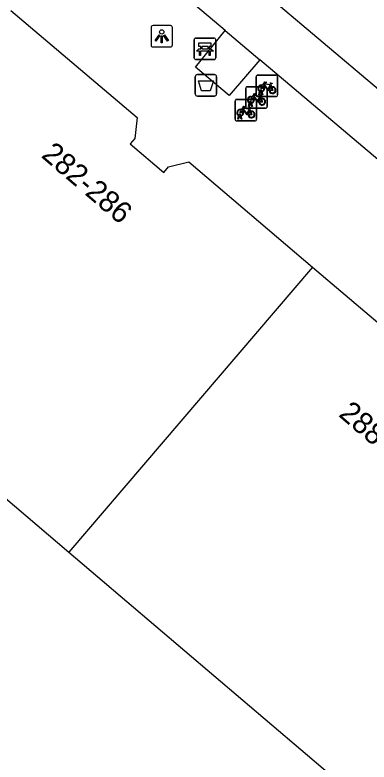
# Model space of a CAD drawing. Extents: x 162347 to 162868, y 381221 to 381813.
# Drawn here: x 162737.04 to 162753.52, y 381577.53 to 381612.3 of the extents above; entities that cross this region are included whole.
import ezdxf

# ---------------------------------------------------------------- set-up
doc = ezdxf.new("R2010")
doc.units = 0
for name, color, linetype in [('IMGEO_Afvalbak', 7, 'Continuous'), ('IMGEO_Bank', 7, 'Continuous'), ('IMGEO_Fietsenrek', 7, 'Continuous'), ('IMGEO_Fietspad_gesloten', 7, 'Continuous'), ('IMGEO_Lichtpunt', 7, 'Continuous'), ('IMGEO_Pand', 7, 'Continuous'), ('IMGEO_Pand_nummerreeks', 7, 'Continuous'), ('IMGEO_Voetpad_open', 7, 'Continuous')]:
    doc.layers.add(name, color=color, linetype=linetype)

msp = doc.modelspace()

# ---------------------------------------------------------------- linework, layer by layer
at = {"layer": 'IMGEO_Afvalbak'}
for p, q in [((162745.432, 381608.623), (162745.432, 381609.423)), ((162745.432, 381609.423), (162745.432, 381608.623)), ((162745.532, 381609.523), (162746.322, 381609.523)), ((162746.322, 381609.523), (162745.532, 381609.523)), ((162746.422, 381609.423), (162746.422, 381608.623)), ((162746.422, 381608.623), (162746.422, 381609.423)), ((162746.322, 381608.523), (162745.532, 381608.523)), ((162745.532, 381608.523), (162746.322, 381608.523))]:
    msp.add_line(p, q, dxfattribs=at)
msp.add_lwpolyline([(162745.575, 381609.237), (162746.279, 381609.237), (162746.13, 381608.767), (162745.724, 381608.767), (162745.575, 381609.237)], dxfattribs=at)
for centre, start, end in [((162745.532, 381609.423), 90, 180), ((162745.532, 381609.423), 90, 180), ((162746.322, 381609.423), 0, 90), ((162746.322, 381609.423), 360, 90), ((162745.532, 381608.623), 180, 270), ((162745.532, 381608.623), 180, 270), ((162746.322, 381608.623), 270, 0), ((162746.322, 381608.623), 270, 0)]:
    msp.add_arc(centre, 0.1, start, end, dxfattribs=at)
at = {"layer": 'IMGEO_Bank'}
for p, q in [((162745.382, 381610.295), (162745.382, 381611.136)), ((162745.382, 381611.136), (162745.382, 381610.295)), ((162745.457, 381611.22), (162746.298, 381611.22)), ((162746.298, 381611.22), (162745.457, 381611.22)), ((162746.382, 381611.145), (162746.382, 381610.304)), ((162746.382, 381610.304), (162746.382, 381611.145)), ((162746.079, 381610.618), (162745.686, 381610.618)), ((162745.691, 381610.726), (162745.691, 381610.832)), ((162745.735, 381610.832), (162745.735, 381610.726)), ((162746.023, 381610.838), (162745.741, 381610.838)), ((162745.741, 381610.72), (162746.023, 381610.72)), ((162746.029, 381610.726), (162746.029, 381610.832)), ((162746.073, 381610.832), (162746.073, 381610.726)), ((162746.307, 381610.22), (162745.466, 381610.22)), ((162745.466, 381610.22), (162746.307, 381610.22))]:
    msp.add_line(p, q, dxfattribs=at)
for points in [[(162745.685, 381610.838), (162745.599, 381610.838), (162745.599, 381610.999), (162746.162, 381610.999), (162746.162, 381610.838), (162746.079, 381610.838)], [(162745.629, 381610.618), (162745.487, 381610.618), (162745.599, 381610.72), (162745.685, 381610.72)], [(162745.679, 381610.611), (162745.679, 381610.404), (162745.636, 381610.404), (162745.636, 381610.611)], [(162746.079, 381610.72), (162746.162, 381610.72), (162746.274, 381610.618), (162746.135, 381610.618)], [(162746.129, 381610.611), (162746.129, 381610.404), (162746.085, 381610.404), (162746.085, 381610.611)]]:
    msp.add_lwpolyline(points, dxfattribs=at)
for centre, radius, start, end in [((162745.46, 381611.142), 0.0779, 92.4484, 184.2845), ((162745.46, 381611.142), 0.0779, 92.4484, 184.2845), ((162746.304, 381611.142), 0.0779, 2.4484, 94.2845), ((162746.304, 381611.142), 0.0779, 2.4484, 94.2845), ((162745.629, 381610.611), 0.00671, 2.8957, 87.1043), ((162745.686, 381610.611), 0.00671, 92.8957, 177.1043), ((162745.684, 381610.831), 0.00671, 2.8957, 87.1043), ((162745.684, 381610.727), 0.00671, 272.8957, 357.1043), ((162745.741, 381610.831), 0.00671, 92.8957, 177.1043), ((162745.741, 381610.727), 0.00671, 182.8957, 267.1043), ((162746.023, 381610.831), 0.00671, 2.8957, 87.1043), ((162746.023, 381610.727), 0.00671, 272.8957, 357.1043), ((162746.08, 381610.831), 0.00671, 92.8957, 177.1043), ((162746.08, 381610.727), 0.00671, 182.8957, 267.1043), ((162746.078, 381610.611), 0.00671, 2.8957, 87.1043), ((162746.135, 381610.611), 0.00671, 92.8957, 177.1043), ((162745.46, 381610.298), 0.0779, 182.4484, 274.2845), ((162745.46, 381610.298), 0.0779, 182.4484, 274.2845), ((162746.304, 381610.298), 0.0779, 272.4484, 4.2845), ((162746.304, 381610.298), 0.0779, 272.4484, 4.2845)]:
    msp.add_arc(centre, radius, start, end, dxfattribs=at)
at = {"layer": 'IMGEO_Fietsenrek'}
for p, q in [((162748.261, 381608.573), (162748.261, 381609.414)), ((162748.261, 381609.414), (162748.261, 381608.573)), ((162748.336, 381609.498), (162749.177, 381609.498)), ((162749.177, 381609.498), (162748.336, 381609.498)), ((162749.261, 381609.423), (162749.261, 381608.582)), ((162749.261, 381608.582), (162749.261, 381609.423)), ((162747.778, 381608.036), (162747.778, 381608.877)), ((162747.778, 381608.877), (162747.778, 381608.036)), ((162747.853, 381608.961), (162748.694, 381608.961)), ((162748.694, 381608.961), (162747.853, 381608.961)), ((162748.778, 381608.886), (162748.778, 381608.045)), ((162748.778, 381608.045), (162748.778, 381608.886)), ((162748.948, 381609.047), (162748.984, 381608.952)), ((162749.186, 381608.498), (162748.345, 381608.498)), ((162748.345, 381608.498), (162749.186, 381608.498)), ((162748.388, 381608.582), (162748.427, 381608.742)), ((162748.422, 381608.582), (162748.388, 381608.582)), ((162748.457, 381608.73), (162748.422, 381608.582)), ((162748.465, 381608.51), (162748.501, 381608.415)), ((162748.499, 381608.754), (162748.498, 381608.758)), ((162748.54, 381608.582), (162748.506, 381608.724)), ((162748.53, 381608.765), (162748.531, 381608.758)), ((162748.538, 381608.728), (162748.573, 381608.582)), ((162748.573, 381608.582), (162748.54, 381608.582)), ((162747.283, 381607.442), (162747.283, 381608.283)), ((162747.283, 381608.283), (162747.283, 381607.442)), ((162747.358, 381608.367), (162748.199, 381608.367)), ((162748.199, 381608.367), (162747.358, 381608.367)), ((162747.905, 381608.045), (162747.944, 381608.205)), ((162747.974, 381608.193), (162747.939, 381608.045)), ((162748.016, 381608.217), (162748.015, 381608.221)), ((162748.057, 381608.045), (162748.023, 381608.187)), ((162748.047, 381608.228), (162748.048, 381608.221)), ((162748.055, 381608.191), (162748.09, 381608.045)), ((162748.283, 381608.292), (162748.283, 381607.451)), ((162748.283, 381607.451), (162748.283, 381608.292)), ((162748.703, 381607.961), (162747.862, 381607.961)), ((162747.862, 381607.961), (162748.703, 381607.961)), ((162747.939, 381608.045), (162747.905, 381608.045)), ((162747.97, 381607.916), (162748.006, 381607.821)), ((162748.09, 381608.045), (162748.057, 381608.045)), ((162747.41, 381607.451), (162747.449, 381607.611)), ((162747.444, 381607.451), (162747.41, 381607.451)), ((162747.479, 381607.599), (162747.444, 381607.451)), ((162747.521, 381607.623), (162747.52, 381607.627)), ((162747.562, 381607.451), (162747.528, 381607.593)), ((162747.552, 381607.634), (162747.553, 381607.627)), ((162747.56, 381607.597), (162747.595, 381607.451)), ((162747.595, 381607.451), (162747.562, 381607.451)), ((162748.208, 381607.367), (162747.367, 381607.367)), ((162747.367, 381607.367), (162748.208, 381607.367))]:
    msp.add_line(p, q, dxfattribs=at)
for points in [[(162748.595, 381608.972), (162748.543, 381608.882), (162748.503, 381608.857), (162748.504, 381608.904), (162748.559, 381608.998)], [(162748.574, 381609.024), (162748.669, 381609.188), (162748.755, 381609.174), (162748.757, 381609.165), (162748.701, 381609.154), (162748.674, 381609.109), (162748.93, 381609.068)], [(162748.87, 381608.78), (162748.82, 381608.78), (162748.629, 381609.031), (162748.61, 381608.999)], [(162748.917, 381609.043), (162748.66, 381609.084), (162748.643, 381609.055), (162748.81, 381608.835), (162748.917, 381609.043)], [(162748.965, 381608.945), (162748.935, 381609.022), (162748.826, 381608.804), (162748.869, 381608.804)], [(162748.899, 381608.804), (162749.019, 381608.803), (162748.975, 381608.917)], [(162748.995, 381608.924), (162749.05, 381608.779), (162748.9, 381608.779)], [(162748.93, 381609.068), (162748.955, 381609.117), (162748.949, 381609.121), (162748.926, 381609.125), (162748.914, 381609.132), (162748.913, 381609.135), (162748.915, 381609.14), (162749.01, 381609.125), (162749.012, 381609.115), (162749.002, 381609.102), (162748.99, 381609.096), (162748.976, 381609.102), (162748.948, 381609.047)], [(162748.091, 381608.487), (162748.186, 381608.651), (162748.272, 381608.637), (162748.274, 381608.628), (162748.218, 381608.617), (162748.191, 381608.572), (162748.447, 381608.531)], [(162748.387, 381608.243), (162748.337, 381608.243), (162748.146, 381608.494), (162748.127, 381608.462)], [(162748.434, 381608.506), (162748.177, 381608.547), (162748.16, 381608.518), (162748.327, 381608.298), (162748.434, 381608.506)], [(162748.447, 381608.531), (162748.472, 381608.58), (162748.466, 381608.584), (162748.443, 381608.588), (162748.431, 381608.595), (162748.43, 381608.598), (162748.432, 381608.603), (162748.527, 381608.588), (162748.529, 381608.578), (162748.519, 381608.565), (162748.507, 381608.559), (162748.493, 381608.565), (162748.465, 381608.51)], [(162748.112, 381608.435), (162748.06, 381608.345), (162748.02, 381608.32), (162748.021, 381608.367), (162748.076, 381608.461)], [(162748.482, 381608.408), (162748.452, 381608.485), (162748.343, 381608.267), (162748.386, 381608.267)], [(162748.416, 381608.267), (162748.536, 381608.266), (162748.492, 381608.38)], [(162748.512, 381608.387), (162748.567, 381608.242), (162748.417, 381608.242)], [(162747.617, 381607.841), (162747.565, 381607.751), (162747.525, 381607.726), (162747.526, 381607.773), (162747.581, 381607.867)], [(162747.596, 381607.893), (162747.691, 381608.057), (162747.777, 381608.043), (162747.779, 381608.034), (162747.723, 381608.023), (162747.696, 381607.978), (162747.952, 381607.937)], [(162747.892, 381607.649), (162747.842, 381607.649), (162747.651, 381607.9), (162747.632, 381607.868)], [(162747.939, 381607.912), (162747.682, 381607.953), (162747.665, 381607.924), (162747.832, 381607.704), (162747.939, 381607.912)], [(162747.987, 381607.814), (162747.957, 381607.891), (162747.848, 381607.673), (162747.891, 381607.673)], [(162747.952, 381607.937), (162747.977, 381607.986), (162747.971, 381607.99), (162747.948, 381607.994), (162747.936, 381608.001), (162747.935, 381608.004), (162747.937, 381608.009), (162748.032, 381607.994), (162748.034, 381607.984), (162748.024, 381607.971), (162748.012, 381607.965), (162747.998, 381607.971), (162747.97, 381607.916)], [(162747.921, 381607.673), (162748.041, 381607.672), (162747.997, 381607.786)], [(162748.017, 381607.793), (162748.072, 381607.648), (162747.922, 381607.648)]]:
    msp.add_lwpolyline(points, dxfattribs=at)
for centre, radius, start, end in [((162748.339, 381609.42), 0.0779, 92.4484, 184.2845), ((162748.339, 381609.42), 0.0779, 92.4484, 184.2845), ((162749.183, 381609.42), 0.0779, 2.4484, 94.2845), ((162749.183, 381609.42), 0.0779, 2.4484, 94.2845), ((162747.856, 381608.883), 0.0779, 92.4484, 184.2845), ((162747.856, 381608.883), 0.0779, 92.4484, 184.2845), ((162748.501, 381608.883), 0.159, 62.6766, 242.1369), ((162748.501, 381608.883), 0.129, 63.3192, 238.903), ((162748.501, 381608.883), 0.129, 283.6043, 43.4302), ((162748.501, 381608.883), 0.159, 283.5766, 46.6042), ((162748.7, 381608.883), 0.0779, 2.4484, 94.2845), ((162748.7, 381608.883), 0.0779, 2.4484, 94.2845), ((162749.028, 381608.799), 0.159, 113.3408, 178.3217), ((162749.028, 381608.799), 0.159, 187.0065, 105.7708), ((162749.028, 381608.799), 0.129, 113.923, 177.9556), ((162749.028, 381608.799), 0.129, 188.6715, 104.5883), ((162748.018, 381608.346), 0.159, 62.6766, 242.1369), ((162748.339, 381608.576), 0.0779, 182.4484, 274.2845), ((162748.339, 381608.576), 0.0779, 182.4484, 274.2845), ((162748.481, 381608.754), 0.0499, 12.8025, 158.6934), ((162748.501, 381608.883), 0.159, 253.9967, 271.7867), ((162748.481, 381608.754), 0.0174, 12.8025, 163.4502), ((162748.501, 381608.883), 0.129, 253.415, 269.0204), ((162749.183, 381608.576), 0.0779, 272.4484, 4.2845), ((162749.183, 381608.576), 0.0779, 272.4484, 4.2845), ((162747.361, 381608.289), 0.0779, 92.4484, 184.2845), ((162747.361, 381608.289), 0.0779, 92.4484, 184.2845), ((162748.018, 381608.346), 0.129, 63.3192, 238.903), ((162747.998, 381608.217), 0.0499, 12.8025, 158.6934), ((162748.018, 381608.346), 0.159, 253.9967, 271.7867), ((162747.998, 381608.217), 0.0174, 12.8025, 163.4502), ((162748.018, 381608.346), 0.129, 253.415, 269.0204), ((162748.018, 381608.346), 0.129, 283.6043, 43.4302), ((162748.018, 381608.346), 0.159, 283.5766, 46.6042), ((162748.205, 381608.289), 0.0779, 2.4484, 94.2845), ((162748.205, 381608.289), 0.0779, 2.4484, 94.2845), ((162748.545, 381608.262), 0.159, 113.3408, 178.3217), ((162748.545, 381608.262), 0.159, 187.0065, 105.7708), ((162748.545, 381608.262), 0.129, 113.923, 177.9556), ((162748.545, 381608.262), 0.129, 188.6715, 104.5883), ((162747.523, 381607.752), 0.159, 62.6766, 242.1369), ((162747.523, 381607.752), 0.129, 63.3192, 238.903), ((162747.523, 381607.752), 0.129, 283.6043, 43.4302), ((162747.523, 381607.752), 0.159, 283.5766, 46.6042), ((162747.856, 381608.039), 0.0779, 182.4484, 274.2845), ((162747.856, 381608.039), 0.0779, 182.4484, 274.2845), ((162748.05, 381607.668), 0.159, 113.3408, 178.3217), ((162748.05, 381607.668), 0.159, 187.0065, 105.7708), ((162748.7, 381608.039), 0.0779, 272.4484, 4.2845), ((162748.7, 381608.039), 0.0779, 272.4484, 4.2845), ((162747.503, 381607.623), 0.0499, 12.8025, 158.6934), ((162747.523, 381607.752), 0.159, 253.9967, 271.7867), ((162747.503, 381607.623), 0.0174, 12.8025, 163.4502), ((162747.523, 381607.752), 0.129, 253.415, 269.0204), ((162748.05, 381607.668), 0.129, 113.923, 177.9556), ((162748.05, 381607.668), 0.129, 188.6715, 104.5883), ((162748.205, 381607.445), 0.0779, 272.4484, 4.2845), ((162748.205, 381607.445), 0.0779, 272.4484, 4.2845), ((162747.361, 381607.445), 0.0779, 182.4484, 274.2845), ((162747.361, 381607.445), 0.0779, 182.4484, 274.2845)]:
    msp.add_arc(centre, radius, start, end, dxfattribs=at)
at = {"layer": 'IMGEO_Fietspad_gesloten'}
for points in [[(162746.831, 381611.57), (162743.076, 381614.743), (162734.239, 381622.209)], [(162743.753, 381617.476), (162759.809, 381603.905)], [(162746.831, 381611.57), (162748.438, 381610.212)], [(162761.023, 381599.578), (162748.438, 381610.212)]]:
    msp.add_lwpolyline(points, dxfattribs=at)
at = {"layer": 'IMGEO_Lichtpunt'}
for p, q in [((162743.372, 381611.712), (162743.372, 381610.905)), ((162743.372, 381611.712), (162743.372, 381610.905)), ((162744.274, 381611.807), (162743.466, 381611.807)), ((162744.274, 381611.807), (162743.466, 381611.807)), ((162744.368, 381610.905), (162744.368, 381611.712)), ((162744.368, 381610.905), (162744.368, 381611.712)), ((162743.466, 381610.811), (162744.274, 381610.811)), ((162743.466, 381610.811), (162744.274, 381610.811))]:
    msp.add_line(p, q, dxfattribs=at)
for points in [[(162743.746, 381611.376), (162743.785, 381611.348), (162743.597, 381611.086), (162743.559, 381611.113), (162743.746, 381611.376)], [(162743.848, 381611.328), (162743.895, 381611.328), (162743.895, 381611.006), (162743.848, 381611.006), (162743.848, 381611.328)], [(162743.958, 381611.348), (162743.996, 381611.375), (162744.183, 381611.113), (162744.144, 381611.085), (162743.958, 381611.348)]]:
    msp.add_lwpolyline(points, dxfattribs=at)
msp.add_circle((162743.871, 381611.51), 0.0994, dxfattribs=at)
for centre, start, end in [((162743.466, 381611.712), 90, 180), ((162743.466, 381611.712), 90, 180), ((162744.274, 381611.712), 0, 90), ((162744.274, 381611.712), 0, 90), ((162743.466, 381610.905), 180, 270), ((162743.466, 381610.905), 180, 270), ((162744.274, 381610.905), 270, 0), ((162744.274, 381610.905), 270, 360)]:
    msp.add_arc(centre, 0.0946, start, end, dxfattribs=at)
at = {"layer": 'IMGEO_Pand'}
for points in [[(162736.849, 381612.501), (162742.724, 381607.528), (162742.611, 381606.552), (162742.402, 381606.301), (162743.961, 381604.974), (162744.187, 381605.228), (162745.129, 381605.46), (162750.894, 381600.568)], [(162750.894, 381600.568), (162739.55, 381587.303)], [(162750.894, 381600.568), (162756.886, 381595.484), (162756.796, 381594.476), (162756.596, 381594.242), (162758.154, 381592.91), (162758.354, 381593.144), (162759.394, 381593.402), (162763.364, 381589.986)], [(162725.513, 381599.243), (162739.55, 381587.303)], [(162739.55, 381587.303), (162753.048, 381575.822)]]:
    msp.add_lwpolyline(points, dxfattribs=at)
at = {"layer": 'IMGEO_Voetpad_open'}
msp.add_lwpolyline([(162748.438, 381610.212), (162747.008, 381608.551), (162745.443, 381609.87), (162746.831, 381611.57)], dxfattribs=at)

# ---------------------------------------------------------------- texts
at = {"layer": 'IMGEO_Pand_nummerreeks'}
for s, rotation, p in [('282-286', 319.469, (162738.219, 381605.71)), ('288-292', 319.4518, (162752.061, 381593.658))]:
    msp.add_text(s, height=1, rotation=rotation, dxfattribs=at).set_placement(p)

doc.saveas('drawing.dxf')
